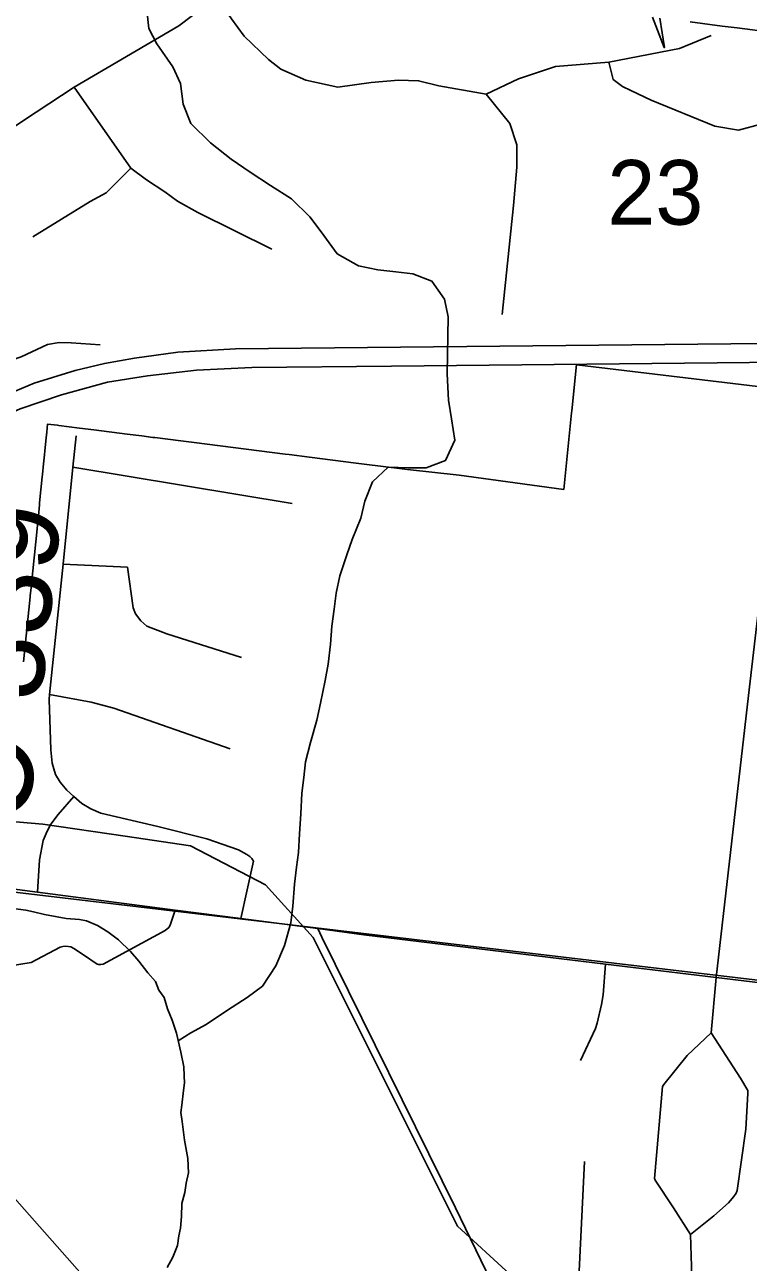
# Model space of a CAD drawing. Extents: x 0 to 34, y -3.9 to 26.2.
# Drawn here: x 4.866 to 5.335, y 14.888 to 15.69 of the extents above; entities that cross this region are included whole.
import ezdxf

# ---------------------------------------------------------------- set-up
doc = ezdxf.new("R2010")
doc.units = 0
for name, color, linetype in [('GM_X_City_Street', 7, 'Continuous'), ('GM_X_County_Road', 7, 'Continuous'), ('GM_X_County_Road_Text', 7, 'Continuous'), ('GM_X_Interchange_Ramps', 7, 'Continuous'), ('GM_X_Interstate_Route', 7, 'Continuous'), ('GM_X_Minor_River', 7, 'Continuous'), ('GM_X_Rail_Line', 7, 'Continuous'), ('GM_X_Section', 7, 'Continuous'), ('GM_X_Section_Text', 7, 'Continuous'), ('GM_X_State_Shield', 7, 'Continuous'), ('GM_X_Township_Road', 7, 'Continuous')]:
    doc.layers.add(name, color=color, linetype=linetype)

msp = doc.modelspace()

# ---------------------------------------------------------------- linework, layer by layer
at = {"layer": 'GM_X_City_Street'}
for p, q in [((4.89691, 15.40334), (5.03917, 15.37974)), ((4.89045, 15.34038), (4.9322, 15.33849)), ((5.00572, 15.11079), (5.01405, 15.14791)), ((5.22488, 14.87348), (5.22871, 14.95344))]:
    msp.add_line(p, q, dxfattribs=at)
for points in [[(5.01405, 15.14791), (5.01283, 15.14963), (5.01164, 15.15107), (5.00976, 15.15232), (5.00436, 15.15538), (4.98365, 15.16238), (4.95196, 15.17044), (4.91495, 15.17901), (4.90847, 15.18191), (4.90258, 15.18542), (4.89754, 15.18992), (4.89293, 15.19403), (4.88856, 15.19914), (4.88558, 15.2041), (4.8835, 15.21147), (4.88256, 15.22013), (4.88147, 15.25283), (4.88179, 15.25593), (4.89045, 15.34038), (4.89691, 15.40334), (4.899, 15.42371)], [(5.31401, 15.07261), (5.33512, 15.25541), (5.34648, 15.3538)], [(4.9322, 15.33849), (4.93596, 15.31219), (4.93749, 15.30837), (4.94085, 15.30372), (4.94283, 15.30196), (4.94482, 15.30028), (4.95771, 15.29528), (5.00631, 15.27994)], [(4.88179, 15.25593), (4.90877, 15.25098), (4.92348, 15.24717), (4.99878, 15.22087)], [(4.87388, 15.1279), (4.8751, 15.14891), (4.87768, 15.16138), (4.88018, 15.16752), (4.88251, 15.17188), (4.88722, 15.17822), (4.89754, 15.18992)], [(4.96319, 15.11631), (4.95992, 15.10644), (4.95905, 15.10491), (4.95681, 15.1031), (4.91646, 15.08128), (4.91489, 15.08101), (4.91343, 15.08098), (4.91266, 15.0813), (4.9037, 15.08729), (4.89752, 15.09139), (4.89547, 15.09243), (4.89219, 15.09285), (4.89035, 15.09275), (4.88864, 15.09221), (4.86982, 15.08241), (4.85649, 15.08008)], [(5.05568, 15.10431), (5.08547, 15.10026), (5.24242, 15.08128), (5.31401, 15.07261), (5.38597, 15.06391), (5.45793, 15.0552), (5.55045, 15.04401), (5.58868, 15.03931), (5.6822, 14.99984)], [(5.22615, 15.01885), (5.23578, 15.03949), (5.23688, 15.04302), (5.23978, 15.05504), (5.24088, 15.06139), (5.24242, 15.08128)], [(5.29869, 14.8646), (5.2974, 14.90603), (5.31251, 14.91817), (5.32221, 14.92665), (5.32554, 14.93059), (5.32715, 14.93286), (5.32772, 14.93449), (5.33327, 14.97423), (5.33475, 14.99748), (5.33465, 14.99927), (5.32991, 15.00738), (5.3109, 15.03675), (5.31401, 15.07261)], [(5.2974, 14.90603), (5.28644, 14.92342), (5.27464, 14.94115), (5.27427, 14.9418), (5.2741, 14.94242), (5.27927, 15.00187), (5.28012, 15.00331), (5.29534, 15.02197), (5.3109, 15.03675)]]:
    msp.add_lwpolyline(points, dxfattribs=at)
at = {"layer": 'GM_X_County_Road'}
msp.add_line((5.14505, 14.92322), (5.16799, 14.87594), dxfattribs=at)
for points in [[(4.87305, 15.63339), (4.89771, 15.64952), (4.96553, 15.68933), (4.97438, 15.69598), (4.9779, 15.70124), (4.98774, 15.71115), (4.98873, 15.72129)], [(4.81437, 15.58205), (4.81467, 15.58298), (4.8202, 15.59141), (4.82784, 15.60208), (4.84017, 15.61189), (4.87305, 15.63339)], [(4.81603, 15.1354), (4.87388, 15.1279), (4.96319, 15.11631), (5.00572, 15.11079), (5.05568, 15.10431)], [(5.05568, 15.10431), (5.05842, 15.09877), (5.14505, 14.92322)]]:
    msp.add_lwpolyline(points, dxfattribs=at)
at = {"layer": 'GM_X_Interchange_Ramps'}
for points in [[(5.27291, 15.69493), (5.28037, 15.67523), (5.28054, 15.67524), (5.2776, 15.69434)], [(5.29734, 15.69185), (5.31804, 15.68923), (5.32771, 15.68801), (5.35093, 15.68508)], [(5.40614, 15.44794), (5.22373, 15.46976), (5.22354, 15.46979), (5.22048, 15.4399), (5.22035, 15.43863), (5.2152, 15.38893), (5.14741, 15.3981), (5.11382, 15.40182), (5.10535, 15.40284), (5.10328, 15.4031), (5.08052, 15.40598), (5.05035, 15.40979), (5.03705, 15.41148), (5.03462, 15.41178), (5.02618, 15.41285), (5.01772, 15.41392), (5.00926, 15.41499), (5.00081, 15.41606), (4.99235, 15.41713), (4.98389, 15.4182), (4.97543, 15.41928), (4.96697, 15.42035), (4.95852, 15.42142), (4.95006, 15.42249), (4.94874, 15.42264), (4.9416, 15.42356), (4.93216, 15.42476), (4.91055, 15.42752), (4.90115, 15.4287), (4.88764, 15.4304), (4.88692, 15.43049), (4.88048, 15.4313), (4.87994, 15.42607), (4.87957, 15.42235), (4.87872, 15.41392), (4.87845, 15.41126), (4.87787, 15.40549), (4.87717, 15.39863), (4.87701, 15.39706), (4.87616, 15.38862), (4.87531, 15.38019), (4.87519, 15.37901), (4.87446, 15.37176), (4.87434, 15.37064), (4.8736, 15.36333), (4.87275, 15.35489), (4.87189, 15.34646), (4.87171, 15.34458), (4.87086, 15.33614), (4.87, 15.32771), (4.86974, 15.32513), (4.86925, 15.32022), (4.86915, 15.31928), (4.8683, 15.31085), (4.86745, 15.30241), (4.86716, 15.29956), (4.86659, 15.29398), (4.86618, 15.28983), (4.86574, 15.28555), (4.86489, 15.27712)]]:
    msp.add_lwpolyline(points, dxfattribs=at)
at = {"layer": 'GM_X_Interstate_Route'}
for points in [[(5.10362, 15.46878), (5.58914, 15.47377), (5.61568, 15.47421), (5.63717, 15.47531), (5.6692, 15.47904), (5.70275, 15.48605), (5.72996, 15.49506), (5.76322, 15.50773), (5.78215, 15.51742), (5.82141, 15.54154), (5.85234, 15.56655), (5.87602, 15.5898), (5.89362, 15.60764), (5.90026, 15.61678), (5.91002, 15.6295), (5.92033, 15.6454), (5.93579, 15.67161), (5.94752, 15.6976), (5.95772, 15.72271), (5.96761, 15.75536)], [(4.74946, 15.38685), (4.76628, 15.39999), (4.78487, 15.41386), (4.79492, 15.42021), (4.80303, 15.42532), (4.8265, 15.43815), (4.85117, 15.44923), (4.87173, 15.45771), (4.89833, 15.4659), (4.91741, 15.47061), (4.93692, 15.47391), (4.96489, 15.47785), (5.0024, 15.48004), (5.58066, 15.48585)], [(4.62867, 15.26705), (4.70028, 15.32884), (4.75774, 15.37553), (4.77455, 15.38867), (4.79314, 15.40254), (4.81184, 15.41543), (4.83377, 15.42793), (4.86272, 15.44109), (4.88948, 15.4503), (4.91931, 15.45842), (4.94519, 15.46259), (4.97699, 15.4661), (5.01296, 15.46785), (5.10362, 15.46878)]]:
    msp.add_lwpolyline(points, dxfattribs=at)
at = {"layer": 'GM_X_Minor_River'}
for points in [[(4.96513, 15.03164), (4.97344, 15.03671), (4.98341, 15.04223), (4.99724, 15.05147), (5.00991, 15.05959), (5.01992, 15.06701), (5.02851, 15.08015), (5.03407, 15.09335), (5.03814, 15.1081), (5.03948, 15.11872), (5.04051, 15.13315), (5.04185, 15.14415), (5.04317, 15.15363), (5.04377, 15.16578), (5.04477, 15.17869), (5.0454, 15.19198), (5.04673, 15.20222), (5.04768, 15.21247), (5.05095, 15.22495), (5.05502, 15.23932), (5.0575, 15.2503), (5.06043, 15.26507), (5.06253, 15.27567), (5.06391, 15.28857), (5.06489, 15.30034), (5.06623, 15.31134), (5.06756, 15.32158), (5.07005, 15.33294), (5.07448, 15.34654), (5.07808, 15.35635), (5.08365, 15.37032), (5.08613, 15.38129), (5.0913, 15.39374), (5.10134, 15.40343), (5.11423, 15.40281), (5.126, 15.40296), (5.13861, 15.40767), (5.14455, 15.42086), (5.14252, 15.43458), (5.14048, 15.44679), (5.13966, 15.46391), (5.14035, 15.50077), (5.1379, 15.51222), (5.12977, 15.52378), (5.11734, 15.52858), (5.10636, 15.52993), (5.09463, 15.53129), (5.08215, 15.53381), (5.06826, 15.54167), (5.0579, 15.55594), (5.05049, 15.56558), (5.03857, 15.57721), (5.02507, 15.58583), (5.01195, 15.59444), (4.99959, 15.60304), (4.98612, 15.61356), (4.97346, 15.62596), (4.96838, 15.6386), (4.96673, 15.65194), (4.96162, 15.66268), (4.95128, 15.6777), (4.94615, 15.68768), (4.94485, 15.69949)], [(4.95799, 14.88467), (4.96167, 14.89136), (4.96463, 14.89884), (4.96564, 14.90527), (4.96659, 14.91017), (4.96727, 14.91774), (4.9676, 14.92609), (4.9694, 14.93324), (4.9704, 14.93928), (4.97181, 14.94607), (4.97141, 14.9552), (4.96922, 14.96708), (4.96867, 14.97242), (4.9678, 14.9793), (4.96688, 14.98504), (4.96746, 14.98996), (4.96859, 14.99942), (4.96916, 15.00433), (4.96896, 15.0089), (4.96881, 15.01461), (4.9669, 15.0242), (4.96397, 15.03648), (4.96126, 15.04496), (4.95813, 15.05231), (4.95614, 15.05961), (4.95253, 15.06433), (4.95047, 15.07011), (4.94537, 15.07565), (4.93958, 15.08311), (4.93413, 15.08942), (4.92645, 15.09696), (4.91943, 15.10219), (4.91276, 15.10627), (4.90565, 15.10923), (4.90113, 15.11017), (4.89242, 15.11092), (4.88676, 15.11191), (4.87845, 15.1134), (4.8713, 15.11521), (4.8664, 15.11618), (4.85808, 15.11728)]]:
    msp.add_lwpolyline(points, dxfattribs=at)
at = {"layer": 'GM_X_Rail_Line'}
for points in [[(6.22888, 14.76326), (5.21557, 14.8749), (5.18022, 14.88026), (5.14629, 14.91135), (5.05275, 15.09861), (5.02186, 15.13272), (4.97316, 15.15786), (4.93075, 15.16415), (4.87734, 15.172), (4.74853, 15.183), (4.69669, 15.16257), (4.66999, 15.13113), (4.66816, 15.12896)], [(4.92086, 14.85963), (4.74311, 15.06041)]]:
    msp.add_lwpolyline(points, dxfattribs=at)
at = {"layer": 'GM_X_Section'}
msp.add_lwpolyline([(4.78471, 16.15816), (5.77753, 16.03722), (5.6843, 15.03017), (4.69633, 15.14722)], close=True, dxfattribs=at)
at = {"layer": 'GM_X_State_Shield'}
msp.add_lwpolyline([(4.92768, 14.1), (5.6066, 14.1), (5.6843, 15.03017), (4.69633, 15.14722), (4.59807, 14.13459)], close=True, dxfattribs=at)
at = {"layer": 'GM_X_Township_Road'}
for points in [[(4.98774, 15.71115), (4.99982, 15.69392), (5.008, 15.68259), (5.02372, 15.66749), (5.03177, 15.66121), (5.048, 15.65404), (5.06879, 15.64962), (5.0904, 15.65255), (5.10812, 15.65412), (5.12111, 15.65373), (5.1343, 15.65036), (5.16483, 15.64507), (5.18019, 15.62616), (5.18491, 15.61219), (5.18491, 15.59781), (5.18255, 15.573), (5.17531, 15.50233)], [(5.24457, 15.66574), (5.29026, 15.6746), (5.31086, 15.68307)], [(5.16483, 15.64507), (5.1859, 15.65511), (5.20992, 15.66298), (5.24457, 15.66574)], [(5.24457, 15.66574), (5.24733, 15.65452), (5.25343, 15.64999), (5.25883, 15.64741)], [(4.89771, 15.64952), (4.93453, 15.59704), (4.94459, 15.58949), (4.95642, 15.5817), (4.96472, 15.57566), (4.97781, 15.56836), (5.02586, 15.54471)], [(5.25883, 15.64741), (5.27194, 15.64113), (5.31329, 15.62439), (5.32865, 15.62164), (5.34302, 15.62557), (5.36113, 15.63424)], [(4.93453, 15.59704), (4.91842, 15.58119), (4.90798, 15.57553), (4.87087, 15.55251)], [(4.80045, 15.47499), (4.8401, 15.47146), (4.8453, 15.47146), (4.85771, 15.47291), (4.86322, 15.47476), (4.88042, 15.48284), (4.88802, 15.48417), (4.89582, 15.48388), (4.91455, 15.48263)]]:
    msp.add_lwpolyline(points, dxfattribs=at)

# ---------------------------------------------------------------- texts
at = {"layer": 'GM_X_County_Road_Text'}
msp.add_text('C-339', height=0.056818, rotation=83.93287, dxfattribs=at).set_placement((4.8676, 15.17075))
at = {"layer": 'GM_X_Section_Text'}
msp.add_text('23', height=0.041856, rotation=0.00001, dxfattribs=at).set_placement((5.24352, 15.5605))

doc.saveas('drawing.dxf')
